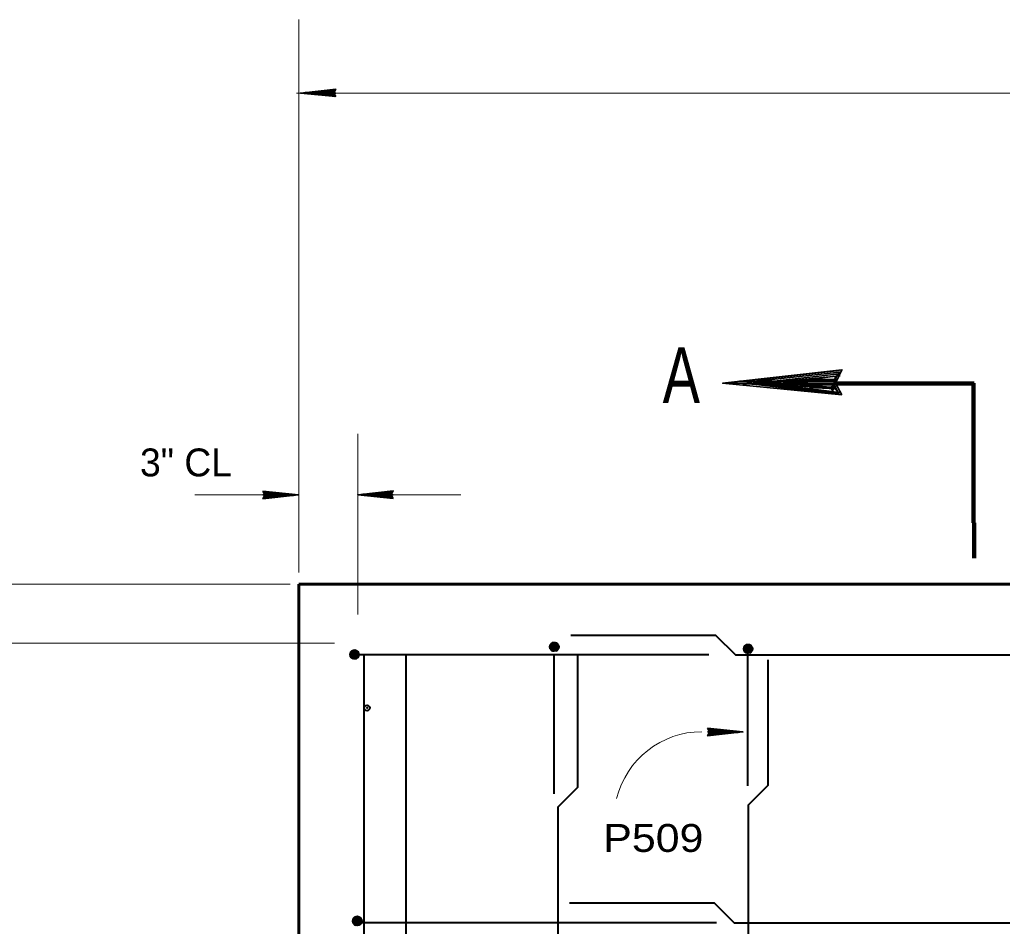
# Model space of a CAD drawing. Extents: x 3.64 to 6.84, y -0.8 to 1.19.
# Drawn here: x 3.9444 to 4.238, y 0.1724 to 0.4432 of the extents above; entities that cross this region are included whole.
import ezdxf

# ---------------------------------------------------------------- set-up
doc = ezdxf.new("R2010")
doc.units = 0
doc.header["$LTSCALE"] = 0.0033
doc.header["$PDMODE"] = 32
doc.header["$PDSIZE"] = 0.00165
doc.layers.add('1', color=7, linetype='Continuous', lineweight=40)

msp = doc.modelspace()

# ---------------------------------------------------------------- linework, layer by layer
at = {"layer": '1', "lineweight": 13}
for p, q in [((4.02775, 0.278083), (4.02775, 0.443167)), ((4.045417, 0.2655), (4.045417, 0.319417)), ((3.99675, 0.30125), (4.017583, 0.30125)), ((4.055333, 0.30125), (4.076167, 0.30125)), ((4.025167, 0.274583), (3.861083, 0.274583)), ((4.038417, 0.256917), (3.861167, 0.256917))]:
    msp.add_line(p, q, dxfattribs=at)
at = {"layer": '1', "lineweight": 35}
for p, q in [((4.038833, 0.42125), (4.02825, 0.42125)), ((4.038583, 0.420417), (4.03075, 0.421417)), ((4.038583, 0.420417), (4.03075, 0.42125)), ((4.038583, 0.42025), (4.03075, 0.421167)), ((4.038583, 0.42025), (4.03075, 0.421167)), ((4.038583, 0.420333), (4.03075, 0.421167)), ((4.038583, 0.422333), (4.03125, 0.4215)), ((4.038583, 0.422167), (4.03125, 0.421417)), ((4.038583, 0.422083), (4.03125, 0.42125)), ((4.038667, 0.421917), (4.031333, 0.421167)), ((4.189333, 0.338333), (4.164583, 0.335583)), ((4.189333, 0.337833), (4.164583, 0.335167)), ((4.189333, 0.331833), (4.16275, 0.335167)), ((4.189333, 0.337417), (4.164583, 0.334583)), ((4.189583, 0.336833), (4.164667, 0.334417)), ((4.190083, 0.334583), (4.154417, 0.334583)), ((4.189333, 0.331833), (4.16275, 0.334583)), ((4.189333, 0.331167), (4.16275, 0.334417)), ((4.189333, 0.331167), (4.16275, 0.334417)), ((4.189333, 0.331583), (4.16275, 0.334417)), ((4.017083, 0.30125), (4.027667, 0.30125)), ((4.01725, 0.300583), (4.024583, 0.301333)), ((4.017333, 0.30225), (4.025167, 0.301333)), ((4.017333, 0.30225), (4.025167, 0.301333)), ((4.017333, 0.302167), (4.025167, 0.301333)), ((4.017333, 0.302083), (4.025167, 0.30125)), ((4.017333, 0.302083), (4.025167, 0.301083)), ((4.017333, 0.300417), (4.024667, 0.30125)), ((4.017333, 0.300333), (4.024667, 0.301083)), ((4.017333, 0.300167), (4.024667, 0.301)), ((4.056, 0.30125), (4.045417, 0.30125)), ((4.05575, 0.300417), (4.047917, 0.301417)), ((4.05575, 0.300417), (4.047917, 0.30125)), ((4.05575, 0.30025), (4.047917, 0.301167)), ((4.05575, 0.30025), (4.047917, 0.301167)), ((4.05575, 0.300333), (4.047917, 0.301167)), ((4.05575, 0.302333), (4.048417, 0.3015)), ((4.05575, 0.302167), (4.048417, 0.301417)), ((4.05575, 0.302083), (4.048417, 0.30125)), ((4.055833, 0.301917), (4.0485, 0.301167)), ((4.149917, 0.230417), (4.1605, 0.230417)), ((4.150083, 0.22975), (4.157417, 0.2305)), ((4.150167, 0.231417), (4.158, 0.2305)), ((4.150167, 0.231417), (4.158, 0.2305)), ((4.150167, 0.231333), (4.158, 0.2305)), ((4.150167, 0.23125), (4.158, 0.230417)), ((4.150167, 0.23125), (4.158, 0.23025)), ((4.150167, 0.229583), (4.1575, 0.230417)), ((4.150167, 0.2295), (4.1575, 0.23025)), ((4.150167, 0.229333), (4.1575, 0.230167))]:
    msp.add_line(p, q, dxfattribs=at)
at = {"layer": '1', "lineweight": 90}
for p, q in [((4.187917, 0.3345), (4.229583, 0.3345)), ((4.229417, 0.334583), (4.229417, 0.292917)), ((4.229583, 0.292833), (4.229583, 0.282333))]:
    msp.add_line(p, q, dxfattribs=at)
at = {"layer": '1', "lineweight": 60}
msp.add_line((4.02775, 0.274583), (4.30575, 0.274583), dxfattribs=at)
at = {"layer": '1'}
for p, q in [((4.103167, 0.255), (4.1035, 0.256917)), ((4.103333, 0.254917), (4.103667, 0.256917)), ((4.103333, 0.255917), (4.104833, 0.255833)), ((4.103333, 0.255833), (4.104833, 0.25575)), ((4.103333, 0.25575), (4.104833, 0.255667)), ((4.103333, 0.255667), (4.104833, 0.255583)), ((4.103333, 0.255583), (4.104833, 0.2555)), ((4.103333, 0.2555), (4.104833, 0.255417)), ((4.103417, 0.257), (4.104917, 0.256917)), ((4.103417, 0.254917), (4.10375, 0.256917)), ((4.103417, 0.256833), (4.104917, 0.25675)), ((4.103417, 0.25675), (4.104917, 0.256667)), ((4.103417, 0.256667), (4.104917, 0.256583)), ((4.103417, 0.256583), (4.104917, 0.2565)), ((4.103417, 0.2565), (4.104917, 0.256417)), ((4.103417, 0.256417), (4.104917, 0.256333)), ((4.103417, 0.256333), (4.104917, 0.25625)), ((4.103417, 0.256333), (4.104917, 0.25625)), ((4.103417, 0.25625), (4.104917, 0.256083)), ((4.103417, 0.256083), (4.104917, 0.255917)), ((4.1035, 0.254917), (4.103917, 0.256917)), ((4.103583, 0.254917), (4.104, 0.256917)), ((4.10375, 0.254917), (4.104083, 0.256833)), ((4.103833, 0.254833), (4.104167, 0.256833)), ((4.103917, 0.254833), (4.104333, 0.256833)), ((4.104, 0.254833), (4.104417, 0.25675)), ((4.104083, 0.254833), (4.1045, 0.25675)), ((4.10425, 0.25475), (4.104667, 0.25675)), ((4.1045, 0.25475), (4.104833, 0.25675)), ((4.104583, 0.25475), (4.104917, 0.256667)), ((4.104667, 0.25475), (4.105, 0.256667)), ((4.10475, 0.254667), (4.105083, 0.256667)), ((4.161083, 0.254417), (4.161417, 0.256333)), ((4.16125, 0.254333), (4.161583, 0.256333)), ((4.161333, 0.256417), (4.162833, 0.256333)), ((4.161333, 0.254333), (4.161667, 0.256333)), ((4.161333, 0.25625), (4.162833, 0.256167)), ((4.161333, 0.256167), (4.162833, 0.256083)), ((4.161333, 0.256083), (4.162833, 0.256)), ((4.161333, 0.256), (4.162833, 0.255917)), ((4.161333, 0.255917), (4.162833, 0.255833)), ((4.161333, 0.255833), (4.162833, 0.25575)), ((4.161333, 0.25575), (4.162833, 0.255667)), ((4.161333, 0.25575), (4.162833, 0.255667)), ((4.161333, 0.255667), (4.162833, 0.2555)), ((4.161333, 0.2555), (4.162833, 0.255333)), ((4.161417, 0.254333), (4.161833, 0.256333)), ((4.1615, 0.254333), (4.161917, 0.256333)), ((4.161667, 0.254333), (4.162, 0.25625)), ((4.16175, 0.25425), (4.162083, 0.25625)), ((4.161833, 0.25425), (4.16225, 0.25625)), ((4.161917, 0.25425), (4.162333, 0.256167)), ((4.162, 0.25425), (4.162417, 0.256167)), ((4.162167, 0.254167), (4.162583, 0.256167)), ((4.162417, 0.254167), (4.16275, 0.256167)), ((4.1625, 0.254167), (4.162833, 0.256083)), ((4.162583, 0.254167), (4.162917, 0.256083)), ((4.162667, 0.254083), (4.163, 0.256083)), ((4.04325, 0.252833), (4.043333, 0.254333)), ((4.045333, 0.253), (4.043333, 0.253417)), ((4.045333, 0.252917), (4.043333, 0.253333)), ((4.045333, 0.252833), (4.043333, 0.253167)), ((4.045333, 0.25275), (4.043333, 0.253083)), ((4.04525, 0.252583), (4.043333, 0.252917)), ((4.043417, 0.252833), (4.0435, 0.254333)), ((4.045417, 0.253333), (4.043417, 0.25375)), ((4.045417, 0.25325), (4.043417, 0.253583)), ((4.045333, 0.253167), (4.043417, 0.2535)), ((4.0435, 0.252833), (4.043583, 0.254333)), ((4.0455, 0.253917), (4.0435, 0.25425)), ((4.0455, 0.253667), (4.0435, 0.254083)), ((4.045417, 0.2535), (4.0435, 0.253917)), ((4.045417, 0.253417), (4.0435, 0.253833)), ((4.045583, 0.254167), (4.043583, 0.2545)), ((4.0455, 0.254083), (4.043583, 0.254417)), ((4.043583, 0.252833), (4.043667, 0.254333)), ((4.0455, 0.254), (4.043583, 0.254333)), ((4.043667, 0.252833), (4.04375, 0.254333)), ((4.04375, 0.252833), (4.043833, 0.254333)), ((4.043833, 0.252833), (4.043917, 0.254333)), ((4.043917, 0.252833), (4.044, 0.254333)), ((4.043917, 0.252833), (4.044, 0.254333)), ((4.044, 0.252833), (4.044167, 0.254333)), ((4.044167, 0.252833), (4.044333, 0.254333)), ((4.044333, 0.25275), (4.044417, 0.25425)), ((4.044417, 0.25275), (4.0445, 0.25425)), ((4.0445, 0.25275), (4.044583, 0.25425)), ((4.044583, 0.25275), (4.044667, 0.25425)), ((4.044667, 0.25275), (4.04475, 0.25425)), ((4.04475, 0.25275), (4.044833, 0.25425)), ((4.044833, 0.25275), (4.044917, 0.25425)), ((4.045, 0.25275), (4.045083, 0.25425)), ((4.045083, 0.25275), (4.045167, 0.25425)), ((4.045167, 0.25275), (4.04525, 0.25425)), ((4.04525, 0.25275), (4.045333, 0.25425)), ((4.045333, 0.25275), (4.045417, 0.25425)), ((4.045833, 0.253583), (4.15025, 0.253583)), ((4.04725, 0.2535), (4.04725, -0.055667)), ((4.103333, 0.255417), (4.104833, 0.255333)), ((4.103333, 0.25525), (4.104833, 0.255167)), ((4.103333, 0.255167), (4.104833, 0.255083)), ((4.103333, 0.255083), (4.104833, 0.255)), ((4.103333, 0.255), (4.104833, 0.254917)), ((4.103333, 0.254917), (4.104833, 0.254833)), ((4.104, 0.253583), (4.104, 0.211917)), ((4.16125, 0.255333), (4.16275, 0.25525)), ((4.16125, 0.25525), (4.16275, 0.255167)), ((4.16125, 0.255167), (4.16275, 0.255083)), ((4.16125, 0.255083), (4.16275, 0.255)), ((4.16125, 0.255), (4.16275, 0.254917)), ((4.16125, 0.254917), (4.16275, 0.254833)), ((4.16125, 0.254833), (4.16275, 0.25475)), ((4.16125, 0.254667), (4.16275, 0.254583)), ((4.16125, 0.254583), (4.16275, 0.2545)), ((4.16125, 0.2545), (4.16275, 0.254417)), ((4.16125, 0.254417), (4.16275, 0.254333)), ((4.16125, 0.254333), (4.16275, 0.25425)), ((4.161833, 0.255083), (4.161833, 0.214333)), ((4.044083, 0.17325), (4.044167, 0.17475)), ((4.046167, 0.173417), (4.044167, 0.173833)), ((4.046167, 0.173333), (4.044167, 0.17375)), ((4.046167, 0.17325), (4.044167, 0.173583)), ((4.046167, 0.173167), (4.044167, 0.1735)), ((4.046083, 0.173), (4.044167, 0.173333)), ((4.04425, 0.17325), (4.044333, 0.17475)), ((4.04625, 0.17375), (4.04425, 0.174167)), ((4.04625, 0.173667), (4.04425, 0.174)), ((4.046167, 0.173583), (4.04425, 0.173917)), ((4.044333, 0.17325), (4.044417, 0.17475)), ((4.046333, 0.174333), (4.044333, 0.174667)), ((4.046333, 0.174083), (4.044333, 0.1745)), ((4.04625, 0.173917), (4.044333, 0.174333)), ((4.04625, 0.173833), (4.044333, 0.17425)), ((4.046417, 0.174583), (4.044417, 0.174917)), ((4.046333, 0.1745), (4.044417, 0.174833)), ((4.044417, 0.17325), (4.0445, 0.17475)), ((4.046333, 0.174417), (4.044417, 0.17475)), ((4.0445, 0.17325), (4.044583, 0.17475)), ((4.044583, 0.17325), (4.044667, 0.17475)), ((4.044667, 0.17325), (4.04475, 0.17475)), ((4.04475, 0.17325), (4.044833, 0.17475)), ((4.04475, 0.17325), (4.044833, 0.17475)), ((4.044833, 0.17325), (4.045, 0.17475)), ((4.045, 0.17325), (4.045167, 0.17475)), ((4.045167, 0.173167), (4.04525, 0.174667)), ((4.04525, 0.173167), (4.045333, 0.174667)), ((4.045333, 0.173167), (4.045417, 0.174667)), ((4.045417, 0.173167), (4.0455, 0.174667)), ((4.0455, 0.173167), (4.045583, 0.174667)), ((4.045583, 0.173167), (4.045667, 0.174667)), ((4.045667, 0.173167), (4.04575, 0.174667)), ((4.045833, 0.173167), (4.045917, 0.174667)), ((4.045917, 0.173167), (4.046, 0.174667)), ((4.046, 0.173167), (4.046083, 0.174667)), ((4.046083, 0.173167), (4.046167, 0.174667)), ((4.046167, 0.173167), (4.04625, 0.174667)), ((4.046417, 0.1735), (4.152583, 0.1735))]:
    msp.add_line(p, q, dxfattribs=at)
at = {"layer": '1', "lineweight": 13}
msp.add_lwpolyline([(4.027083, 0.42125), (4.329917, 0.42125), (4.610417, 0.42125)], dxfattribs=at)
at = {"layer": '1', "lineweight": 35}
for points in [[(4.038833, 0.420167), (4.02825, 0.42125), (4.038833, 0.422417), (4.03825, 0.42125)], [(4.038083, 0.421167), (4.033417, 0.421083), (4.033417, 0.421167), (4.034333, 0.421167), (4.038083, 0.421083), (4.035083, 0.421), (4.03825, 0.420917), (4.036, 0.420833), (4.03825, 0.42075), (4.03475, 0.421), (4.030083, 0.421167), (4.031, 0.421417), (4.02975, 0.421417), (4.038083, 0.421417), (4.035667, 0.421583), (4.03825, 0.421583), (4.032917, 0.421167), (4.03825, 0.421833)], [(4.190083, 0.331083), (4.154417, 0.334583), (4.190083, 0.338583), (4.188167, 0.334583)], [(4.187667, 0.334417), (4.171833, 0.334083), (4.171833, 0.334417), (4.174833, 0.334417), (4.187667, 0.334083), (4.177417, 0.333833), (4.188167, 0.333417), (4.180417, 0.333333), (4.188167, 0.332917), (4.176333, 0.333833), (4.1605, 0.334417), (4.163583, 0.335167), (4.159417, 0.335167), (4.187667, 0.335167), (4.179333, 0.335667), (4.188167, 0.335667), (4.170167, 0.334417), (4.188167, 0.336667)], [(4.017083, 0.302333), (4.027667, 0.30125), (4.017083, 0.300083), (4.017667, 0.30125)], [(4.017833, 0.301333), (4.0225, 0.301417), (4.0225, 0.301333), (4.021583, 0.301333), (4.017833, 0.301417), (4.020833, 0.3015), (4.017667, 0.301583), (4.019917, 0.301667), (4.017667, 0.30175), (4.021167, 0.3015), (4.025833, 0.301333), (4.024917, 0.301083), (4.026167, 0.301083), (4.017833, 0.301083), (4.02025, 0.300917), (4.017667, 0.300917), (4.023, 0.301333), (4.017667, 0.300667)], [(4.056, 0.300167), (4.045417, 0.30125), (4.056, 0.302417), (4.055417, 0.30125)], [(4.05525, 0.301167), (4.050583, 0.301083), (4.050583, 0.301167), (4.0515, 0.301167), (4.05525, 0.301083), (4.05225, 0.301), (4.055417, 0.300917), (4.053167, 0.300833), (4.055417, 0.30075), (4.051917, 0.301), (4.04725, 0.301167), (4.048167, 0.301417), (4.046917, 0.301417), (4.05525, 0.301417), (4.052833, 0.301583), (4.055417, 0.301583), (4.050083, 0.301167), (4.055417, 0.301833)], [(4.149917, 0.2315), (4.1605, 0.230417), (4.149917, 0.22925), (4.1505, 0.230417)], [(4.150667, 0.2305), (4.155333, 0.230583), (4.155333, 0.2305), (4.154417, 0.2305), (4.150667, 0.230583), (4.153667, 0.230667), (4.1505, 0.23075), (4.15275, 0.230833), (4.1505, 0.230917), (4.154, 0.230667), (4.158667, 0.2305), (4.15775, 0.23025), (4.159, 0.23025), (4.150667, 0.23025), (4.153083, 0.230083), (4.1505, 0.230083), (4.155833, 0.2305), (4.1505, 0.229833)]]:
    msp.add_lwpolyline(points, close=True, dxfattribs=at)
for points in [[(4.038083, 0.421167), (4.0385, 0.420417), (4.03825, 0.420667), (4.038083, 0.421), (4.037833, 0.420917), (4.038, 0.420583), (4.038167, 0.421333), (4.038333, 0.421833), (4.038583, 0.42225)], [(4.187667, 0.334417), (4.188917, 0.331833), (4.188167, 0.332667), (4.187667, 0.333833), (4.186667, 0.333417), (4.187333, 0.332333), (4.187833, 0.334917), (4.188417, 0.336667), (4.189333, 0.337917)], [(4.017833, 0.301333), (4.017417, 0.302083), (4.017667, 0.301833), (4.017833, 0.3015), (4.018083, 0.301583), (4.017917, 0.301917), (4.01775, 0.301167), (4.017583, 0.300667), (4.017333, 0.30025)], [(4.05525, 0.301167), (4.055667, 0.300417), (4.055417, 0.300667), (4.05525, 0.301), (4.055, 0.300917), (4.055167, 0.300583), (4.055333, 0.301333), (4.0555, 0.301833), (4.05575, 0.30225)], [(4.150667, 0.2305), (4.15025, 0.23125), (4.1505, 0.231), (4.150667, 0.230667), (4.150917, 0.23075), (4.15075, 0.231083), (4.150583, 0.230333), (4.150417, 0.229833), (4.150167, 0.229417)]]:
    msp.add_lwpolyline(points, dxfattribs=at)
at = {"layer": '1', "lineweight": 60}
msp.add_lwpolyline([(3.944417, -0.142083), (3.944417, -0.05875), (4.02775, -0.05875), (4.02775, 0.274583)], dxfattribs=at)
at = {"layer": '1'}
for points in [[(4.517583, 0.25925), (4.473917, 0.25925), (4.468, 0.253333), (4.25325, 0.253333), (4.158333, 0.253333), (4.152417, 0.25925), (4.109083, 0.25925)], [(4.104167, 0.2545), (4.103833, 0.257083), (4.103333, 0.25475), (4.104417, 0.257083), (4.104833, 0.254667), (4.105167, 0.256667), (4.103083, 0.256667), (4.105417, 0.25575), (4.102833, 0.256), (4.105167, 0.255), (4.102833, 0.255333), (4.105417, 0.256167), (4.103667, 0.254583), (4.1035, 0.257), (4.105333, 0.255333), (4.102917, 0.256417), (4.103333, 0.25475), (4.104833, 0.254667), (4.105417, 0.25575), (4.105167, 0.256667), (4.104417, 0.257083), (4.1035, 0.257), (4.102917, 0.256417), (4.104, 0.25575), (4.104917, 0.256917), (4.105167, 0.255), (4.104, 0.25575), (4.1035, 0.254667), (4.102833, 0.255667), (4.103917, 0.25575), (4.105167, 0.256583), (4.103917, 0.254583), (4.103583, 0.255917), (4.103083, 0.256667)], [(4.162083, 0.253917), (4.16175, 0.2565), (4.16125, 0.254167), (4.162333, 0.2565), (4.16275, 0.254083), (4.163083, 0.256083), (4.161, 0.256083), (4.163333, 0.255167), (4.16075, 0.255417), (4.163083, 0.254417), (4.16075, 0.25475), (4.163333, 0.255583), (4.161583, 0.254), (4.161417, 0.256417), (4.16325, 0.25475), (4.160833, 0.255833), (4.16125, 0.254167), (4.16275, 0.254083), (4.163333, 0.255167), (4.163083, 0.256083), (4.162333, 0.2565), (4.161417, 0.256417), (4.160833, 0.255833), (4.161917, 0.255167), (4.162833, 0.256333), (4.163083, 0.254417), (4.161917, 0.255167), (4.161417, 0.254083), (4.16075, 0.255083), (4.161833, 0.255167), (4.163083, 0.256), (4.161833, 0.254), (4.1615, 0.255333), (4.161, 0.256083)], [(4.04575, 0.253583), (4.043167, 0.25325), (4.0455, 0.25275), (4.043167, 0.253833), (4.045583, 0.25425), (4.043583, 0.254583), (4.043583, 0.2525), (4.0445, 0.254833), (4.04425, 0.25225), (4.04525, 0.254583), (4.044917, 0.25225), (4.044083, 0.254833), (4.045667, 0.253083), (4.04325, 0.252917), (4.044917, 0.25475), (4.043833, 0.252333), (4.0455, 0.25275), (4.045583, 0.25425), (4.0445, 0.254833), (4.043583, 0.254583), (4.043167, 0.253833), (4.04325, 0.252917), (4.043833, 0.252333), (4.0445, 0.253417), (4.043333, 0.254333), (4.04525, 0.254583), (4.0445, 0.253417), (4.045583, 0.252917), (4.044583, 0.25225), (4.0445, 0.253333), (4.043667, 0.254583), (4.045667, 0.253333), (4.044333, 0.253), (4.043583, 0.2525)], [(4.05975, 0.253583), (4.05975, -0.000333), (4.065667, -0.00625), (4.065667, -0.0525)], [(4.111083, 0.253167), (4.111083, 0.213833), (4.105167, 0.207917), (4.105167, -0.000417), (4.111083, -0.006333), (4.111083, -0.052583)], [(4.167917, 0.252), (4.167917, 0.214417), (4.162, 0.2085), (4.162, 0.000167), (4.167917, -0.00575), (4.167917, -0.052)], [(4.517167, 0.17925), (4.4735, 0.17925), (4.467583, 0.173333), (4.252833, 0.173333), (4.157917, 0.173333), (4.152, 0.17925), (4.108667, 0.17925)], [(4.046583, 0.174), (4.044, 0.173667), (4.046333, 0.173167), (4.044, 0.17425), (4.046417, 0.174667), (4.044417, 0.175), (4.044417, 0.172917), (4.045333, 0.17525), (4.045083, 0.172667), (4.046083, 0.175), (4.04575, 0.172667), (4.044917, 0.17525), (4.0465, 0.1735), (4.044083, 0.173333), (4.04575, 0.175167), (4.044667, 0.17275), (4.046333, 0.173167), (4.046417, 0.174667), (4.045333, 0.17525), (4.044417, 0.175), (4.044, 0.17425), (4.044083, 0.173333), (4.044667, 0.17275), (4.045333, 0.173833), (4.044167, 0.17475), (4.046083, 0.175), (4.045333, 0.173833), (4.046417, 0.173333), (4.045417, 0.172667), (4.045333, 0.17375), (4.0445, 0.175), (4.0465, 0.17375), (4.045167, 0.173417), (4.044417, 0.172917)]]:
    msp.add_lwpolyline(points, dxfattribs=at)
for centre in [(4.104117, 0.255833), (4.162033, 0.25525), (4.044417, 0.253533), (4.04525, 0.17395)]:
    msp.add_circle(centre, 0.00132, dxfattribs=at)
at = {"layer": '1', "lineweight": 13}
msp.add_arc((4.148262, 0.204202), 0.026298, 90.20866, 165.95631, dxfattribs=at)
at = {"layer": '1'}
msp.add_point((4.048167, 0.237583), dxfattribs=at)

# ---------------------------------------------------------------- texts
for s, height, width, p in [('A', 0.01667, 0.75, (4.1365, 0.328667)), ('P509', 0.008334, 1.15, (4.11875, 0.194583))]:
    msp.add_text(s, height=height, dxfattribs=dict(at, width=width)).set_placement(p)
msp.add_text('3" CL', height=0.008334, dxfattribs=at).set_placement((3.980333, 0.30675))

doc.saveas('drawing.dxf')
